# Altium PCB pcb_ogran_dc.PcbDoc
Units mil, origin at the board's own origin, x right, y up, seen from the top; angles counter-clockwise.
Board outline 1285 x 1965 mil, 2 copper layers (Top Layer, Bottom Layer); 22 components, 14 nets, 57 pads, 0 vias.
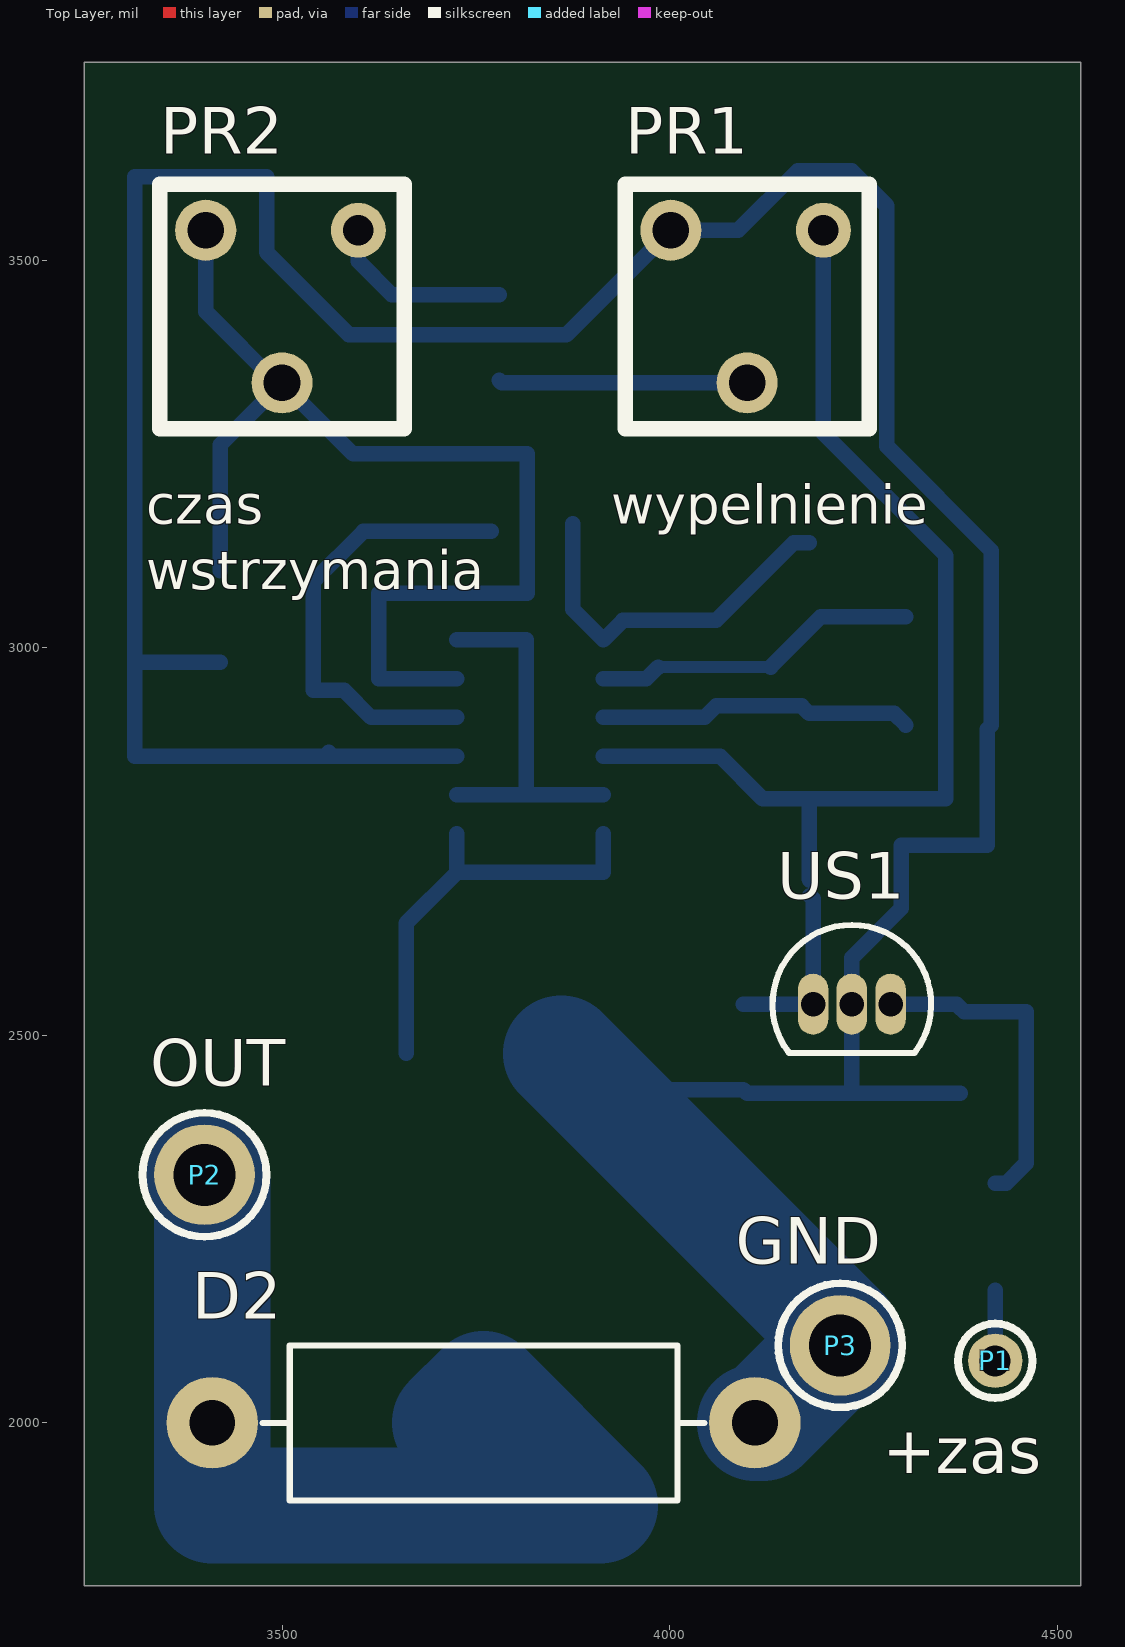
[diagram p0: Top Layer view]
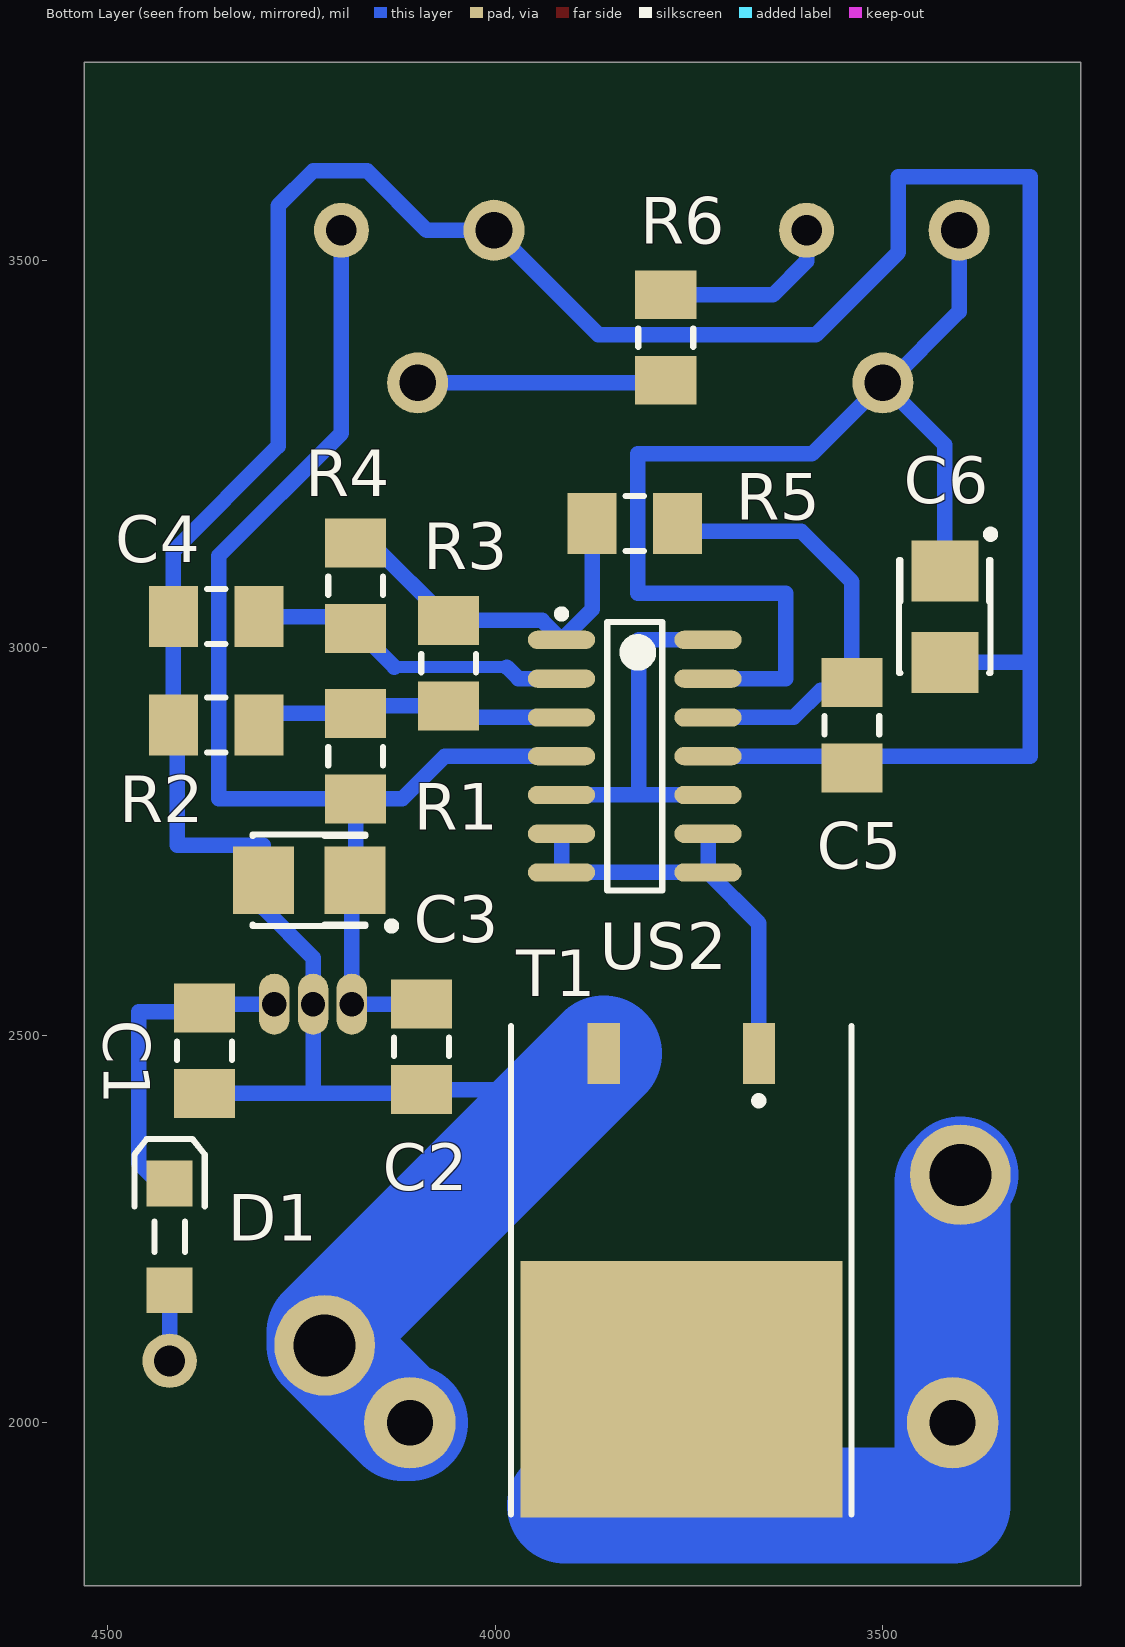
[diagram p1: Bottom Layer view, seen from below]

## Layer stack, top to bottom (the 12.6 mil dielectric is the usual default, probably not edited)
Top Layer: signal copper 1.4
Dielectric: dielectric 12.6, FR-4, Dk 4.8
Bottom Layer: signal copper 1.4

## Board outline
3245,1790 3245,3755 4530,3755 4530,1790

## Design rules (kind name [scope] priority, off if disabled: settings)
Clearance [All] p1: gap=10
PolygonConnect [All] p1: connectstyle=Relief reliefconductorwidth=10 reliefentries=4 polygonreliefangle="90 Angle"
RoomDefinition sch_ogran_dc [InComponentClass('sch_ogran_dc')] p1: confinementstyle=ConfineIn formatcopy=TRUE lockcomponents=FALSE outline 0,0 2000,0 2000,1000 0,1000
RoutingVias [All] p1: holewidth=28 width=50 viastyle="Through Hole" minholewidth=28 minwidth=50 maxholewidth=28 maxwidth=50
SilkscreenOverComponentPads [All] p1: minsilkscreentomaskgap=10
SolderMaskExpansion [All] p1: expansion=4
Width [All] p1: maxlimit=200 minlimit=10 preferedwidth=50
27 further rules are at their usual default settings.

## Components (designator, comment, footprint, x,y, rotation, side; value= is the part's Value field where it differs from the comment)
C1 "100n" MELF-1206 4375,2480 r90 bottom
C2 "100n" MELF-1206 4095,2485 r90 bottom
C3 "22u/16V B" "Tantal B 3528-1411" 4240,2700 r0 bottom
C4 "10n" MELF-1206 4360,3040 r0 bottom
C5 "3,3n" MELF-1206 3540,2900 r270 bottom
C6 "22u/16V B" "Tantal B 3528-1411" 3420,3040 r270 bottom
D1 "1N4148" "dioda MINIMELF" 4420,2240 r90 bottom
D2 "43V" "dioda 17,5mm dwukier" 3760,2000 r180 top
P1 "+ zas" "pad fi 1mm" 4420,2080 r180 top
P2 "wyjście" "pad fi 2mm" 3400,2320 r0 top
P3 "GND" "pad fi 2mm" 4220,2100 r0 top
PR1 "20k" "pot mont poziom" 4100,3440 r180 top
PR2 "200k" "pot mont poziom" 3500,3440 r180 top
R1 "2,7k" MELF-1206 4180,2860 r270 bottom
R2 "2,7k" MELF-1206 4360,2900 r180 bottom
R3 "2,7k" MELF-1206 4060,2980 r90 bottom
R4 "2,7k" MELF-1206 4180,3080 r90 bottom
R5 "2,7k" MELF-1206 3820,3160 r180 bottom
R6 "2,7k" MELF-1206 3780,3400 r270 bottom
T1 "IRF540NS" D2PAK 3760,2260 r0 bottom
US1 "78L09" LP03 4235,2540 r270 top
US2 "TL084" D014_N 3820,2860 r180 bottom

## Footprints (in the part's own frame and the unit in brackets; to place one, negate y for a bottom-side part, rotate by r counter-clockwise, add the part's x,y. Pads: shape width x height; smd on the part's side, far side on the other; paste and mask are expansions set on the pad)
D2PAK [mm] "D2-PAK/TO-263-AB; 3 Leads (1 Cropped); Body 15.5 (inc. leads) x 10.5 mm (LxW max)"
  rect 1.05x2 smd: 1(-2.54,-5.5) 3(2.54,-5.5)
  rect 10.55x8.4 smd: 2(0,5.5)
  silkscreen extent -5.58,-6.4 5.58,9.6
D014_N [mm] "SOIC, 14-Leads, Body 8.7x3.9mm, Pitch 1.27mm, IPC Medium Density"
  oval 2.2x0.6 smd: 1(-2.4,3.81) 2(-2.4,2.54) 3(-2.4,1.27) 4(-2.4,0) 5(-2.4,-1.27) 6(-2.4,-2.54) 7(-2.4,-3.81) 8(2.4,-3.81) 9(2.4,-2.54) 10(2.4,-1.27) 11(2.4,0) 12(2.4,1.27) 13(2.4,2.54) 14(2.4,3.81)
  silkscreen extent -2.53,-4.4 0.9,4.78, body extent -2,-4.38 2,4.38, height 1.75
"dioda 17,5mm dwukier" [mm]
  round 3 hole 1.5: 1(-8.89,0) 2(8.89,0)
  silkscreen extent -7.24,-2.54 7.24,2.54, body extent -6.35,-2.54 6.35,2.54, height 5.08
"dioda MINIMELF" [mm] "SMT LED; 2 Flat Leads"
  rect 1.5x1.5 smd: 1(-1.75,0) 2(1.75,0)
  silkscreen extent -0.5,-1.15 3.2,1.15
LP03 [mm] "TO, Flat Index; 3 In-Line, Axial Leads; Body Dia. 4.8mm; Leads 0.56 x 0.41 mm (max)"
  oval 2x1 hole 0.8: 1(0,-1.27) 2(0,0) 3(0,1.27)
  silkscreen extent -2.6,-2.6 1.6,2.6
MELF-1206 [mm] "Metal Electrode Face (MELF) Resistor; Body 3.2 x 1.8 mm (LxDia)"
  rect 1.6x2 smd: 1(-1.4,0) 2(1.4,0)
  silkscreen extent -0.3,-0.9 0.3,0.9, body extent -2.3,-1.1 2.3,1.1, height 1.85
"pad fi 1mm" [mil]
  round 70 hole 40: 1(0,0)
  silkscreen extent -48,-48 48,48
"pad fi 2mm" [mil]
  round 130 hole 80: 1(0,0)
  silkscreen extent -80,-80 80,80
"pot mont poziom" [mm]
  round 1.8 hole 1: a(-2.5,-2.5)
  round 2 hole 1.2: b(2.5,-2.5) c(0,2.5)
  silkscreen extent -4,-4 4,4
"Tantal B 3528-1411" [mm] "Capacitor, SM Tantalum; Body 3.5 x 2.8 mm (LxW typ)"
  rect 2x2.2 smd: 1(-1.5,0) 2(1.5,0)
  silkscreen extent -2.82,-1.5 1.85,1.62, body extent -2.6,-1.2 2.6,1.2, height 2.5

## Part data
C1 C2 C4 C5: library part kondensator
C3 C6: library part "kond biegunowy", "Polarized Capacitor"
D1: library part Diode, "Default Diode"
D2: library part "Transil dwukierunkowy"
P1 P2 P3: library part Pad, "Pad"
PR1 PR2: library part "pot mont"
R1 R2 R3 R4 R5 R6: library part rezystor
T1: "HEXFET Power MOSFET"
US1: library part µA78L09ACLP, "Positive-Voltage Regulator"
US2: library part TL084D, "JFET-Input Operational Amplifier"

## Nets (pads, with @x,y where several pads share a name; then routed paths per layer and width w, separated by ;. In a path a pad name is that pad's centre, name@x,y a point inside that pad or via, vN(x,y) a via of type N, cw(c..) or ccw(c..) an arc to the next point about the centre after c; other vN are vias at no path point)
GND: C1.1 C2.1 C3.2 C4.2 C5.2 C6.2 D2.1 P3.1 PR1.b R2.1 T1.3 US1.2 US2.11 | length 5050.9
  Bottom Layer w20: C6.2 3310.94,2980.94 3310,2980 ; C5.2@3556.06,2860.94 C5.2@3560,2864.88 ; US2.11 3310,2860 3310,2980 ; T1.3 3943.46,2476.54 3990.12,2429.88 C2.1 4100,2424.88 4235,2424.88 ; C1.1 4235,2424.88 ; 3310,2980 3310,3607.5 3480,3607.5 3480,3510 3586.38,3403.62 3866.77,3403.62 PR1.b 4088.43,3538.43 4165,3615 4235,3615 4280,3570 4280,3260 4415.12,3124.88 C4.2 R2.1 4410,2894.88 4410,2745 4299.06,2745 4299.06,2664.06 4235,2600 US1.2 4235,2424.88
  Bottom Layer w150: T1.3 4220,2116.54 P3.1 4120,2000 D2.1
NetC1_2: C1.2 D1.2 US1.3 | length 425
  Bottom Layer w20: US1.3 4370.12,2540 C1.2 4380.12,2530 4460,2530 4460,2335 4433.9,2308.9 D1.2
NetC2_2: C2.2 C3.1 PR1.a R1.2 US1.1 US2.4 | length 1600.5
  Bottom Layer w20: US2.4 4065,2860 4120.12,2804.88 R1.2 ; C2.2@4095.12,2540 US1.1 4185,2675.94 C3.1@4180.94,2680 ; C3.1 4180,2700.94 R1.2 ; PR1.a 4198.43,3276.57 4356.38,3118.62 4356.38,2804.88 R1.2
NetC4_1: C4.1 R4.1 US2.2 | length 423.5
  Bottom Layer w15: 3985,2975 4130.12,2975
  Bottom Layer w20: US2.2 3970,2960 3985,2975 ; 4130.12,2975 R4.1 4195.12,3040 C4.1
NetC5_1: C5.1 R5.2 US2.12 | length 596.9
  Bottom Layer w20: US2.12 3615,2910 3580,2945 3540,2945 3540,3085 3605,3150 3734.88,3150 R5.2@3770,3150
NetC6_1: C6.1 PR2.b PR2.c US2.13 | length 1416.1
  Bottom Layer w20: 3401.57,3498.43 3401.57,3433.43 PR2.c@3496.71,3338.29 ; C6.1 3420,3261.57 PR2.c@3496.71,3338.29 ; PR2.c@3500,3335 PR2.c@3496.71,3338.29 ; US2.13 3625,2960 3625,3070 3816.38,3070 3816.38,3250 3591.57,3250 PR2.c PR2.c@3496.71,3338.29
NetD1_1: D1.1 P1.1 | length 91.1
  Bottom Layer w20: P1.1 D1.1
NetD2_2: D2.2 P2.1 T1.2 | length 1204.3
  Bottom Layer w150: P2.1 3410,2310 D2.2 3410,1893.46 3760,1893.46 3910,1893.46 T1.2 T1.2@3716.54,2000
NetPR1_c: PR1.c R6.2 | length 321.4
  Bottom Layer w20: R6.2 3783.31,3341.57 PR1.c
NetPR2_a: PR2.a R6.1 | length 239.5
  Bottom Layer w20: PR2.a 3598.43,3498.43 3641.73,3455.12 R6.1
NetR1_1: R1.1 R2.2 R3.1 US2.3 | length 406.9
  Bottom Layer w20: US2.3 4045.12,2910 R3.1 4170.24,2924.88 R1.1 4289.76,2915.12 R2.2
NetR3_2: R3.2 R4.2 R5.1 US2.1 | length 483.6
  Bottom Layer w20: R5.1 3875.12,3049.37 US2.1 3939.61,3035.12 R3.2 4160,3135.12 R4.2
NetT1_1: T1.1 US2.6 US2.7 US2.8 US2.9 | length 549.6
  Bottom Layer w20: T1.1 3660,2644.49 US2.8 ; US2.9 US2.8 ; US2.6 US2.7 US2.8
NetUS2_5: US2.5 US2.10 US2.14 | length 478.5
  Bottom Layer w20: US2.10 3815,2810 ; US2.14 3815,3010 3815,2810 ; US2.5 3815,2810

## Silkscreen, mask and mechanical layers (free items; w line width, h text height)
Top Overlay:
  text "czas" at 3325,3160 h50
  text "wypelnienie" at 3925,3160 h50
  text "wstrzymania" at 3325,3075 h50
  text "OUT" at 3330,2435 h60
  text "GND" at 4085,2205 h60
  text "+zas" at 4275,1935 h60
Mechanical 1:
  the board outline again, w10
